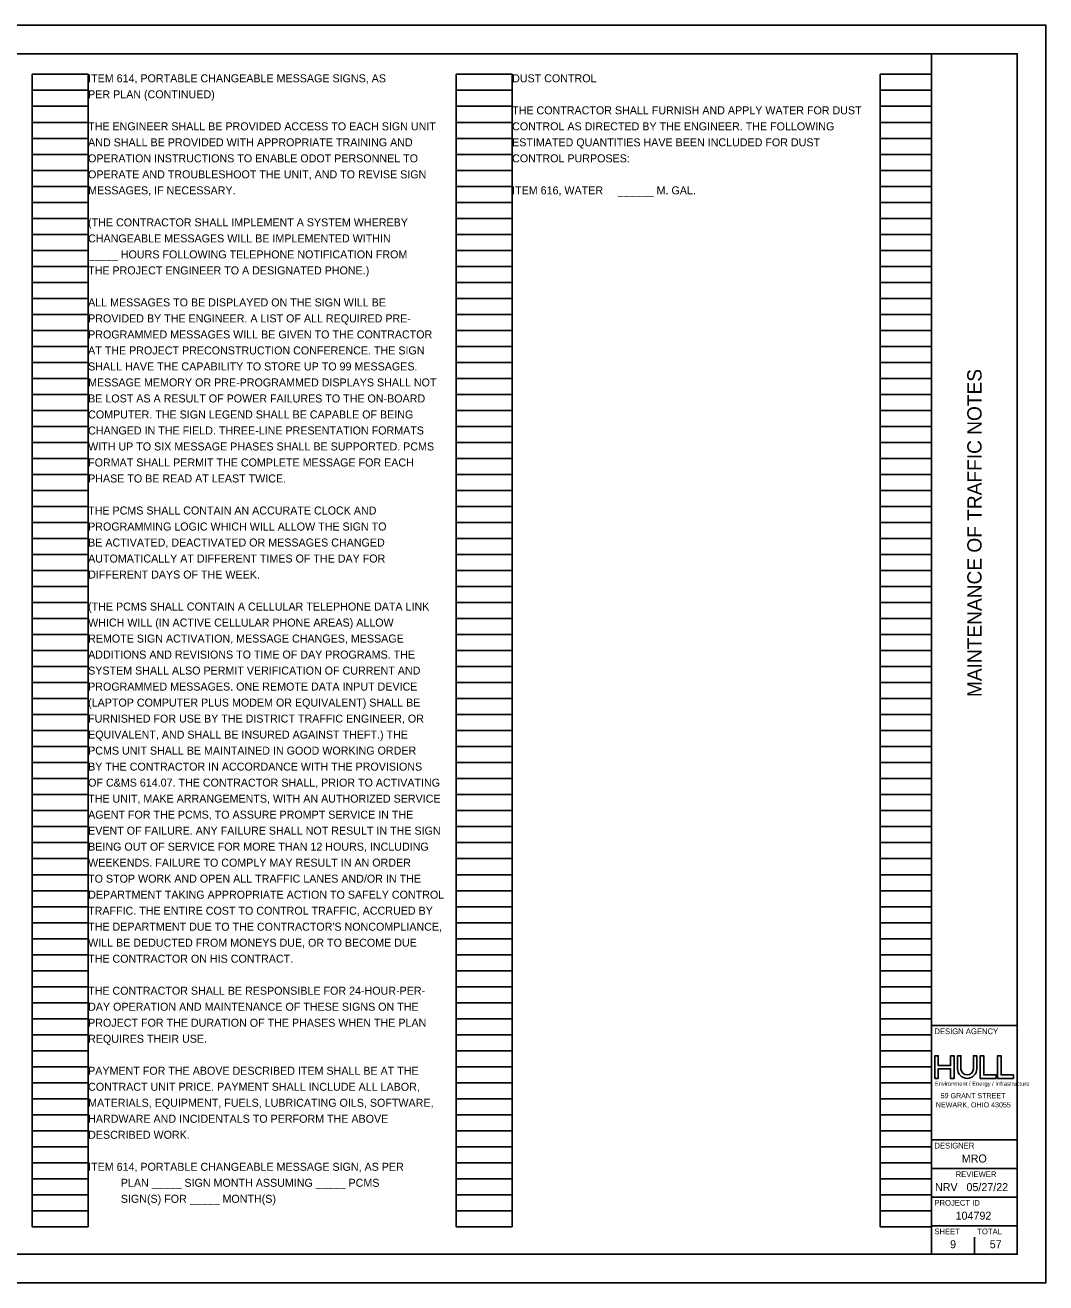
# Model space of a CAD drawing. Extents: x -7.5 to 34, y 0 to 22.
# Drawn here: x 16.14 to 34, y 0 to 22 of the extents above; entities that cross this region are included whole.
import ezdxf

# ---------------------------------------------------------------- set-up
doc = ezdxf.new("R2010")
doc.units = 0
for name, color, linetype in [('Default', 7, 'Continuous'), ('SH_Border', 7, 'Continuous'), ('SH_Cut_Line', 7, 'Continuous'), ('SH_Data', 7, 'Continuous'), ('SH_Text', 7, 'Continuous')]:
    doc.layers.add(name, color=color, linetype=linetype)

msp = doc.modelspace()

# ---------------------------------------------------------------- linework, layer by layer
at = {"layer": 'Default'}
for p, q in [((32.623, 3.637), (32.623, 3.637)), ((32.623, 3.637), (32.623, 3.637)), ((32.623, 3.577), (32.623, 3.577))]:
    msp.add_line(p, q, dxfattribs=at)
for points in [[(32.394, 3.973), (32.333, 3.973), (32.333, 3.799), (32.118, 3.799), (32.118, 3.973), (32.058, 3.973), (32.058, 3.577), (32.118, 3.577), (32.118, 3.745), (32.333, 3.745), (32.333, 3.577), (32.394, 3.577)], [(32.912, 3.973), (32.852, 3.973), (32.852, 3.577), (33.128, 3.577), (33.128, 3.637), (32.912, 3.637)], [(32.852, 3.973), (32.852, 3.577), (33.128, 3.577), (33.128, 3.637), (32.912, 3.637), (32.912, 3.973)], [(33.217, 3.973), (33.156, 3.973), (33.156, 3.577), (33.433, 3.577), (33.433, 3.637), (33.217, 3.637)], [(33.156, 3.973), (33.156, 3.577), (33.433, 3.577), (33.433, 3.637), (33.217, 3.637), (33.217, 3.973)]]:
    msp.add_lwpolyline(points, close=True, dxfattribs=at)
for points in [[(32.394, 3.973), (32.394, 3.973), (32.394, 3.577), (32.333, 3.577), (32.333, 3.745), (32.118, 3.745), (32.118, 3.577), (32.058, 3.577), (32.058, 3.973), (32.118, 3.973), (32.118, 3.799), (32.333, 3.799), (32.333, 3.973), (32.394, 3.973)], [(32.514, 3.746), (32.514, 3.973), (32.454, 3.973), (32.454, 3.746)], [(32.454, 3.746), (32.454, 3.973), (32.514, 3.973), (32.514, 3.746)], [(32.792, 3.746), (32.792, 3.973), (32.731, 3.973), (32.731, 3.746)], [(32.731, 3.746), (32.731, 3.973), (32.792, 3.973), (32.792, 3.746)]]:
    msp.add_lwpolyline(points, dxfattribs=at)
for radius, start, end in [(0.169, 180, 270.0443), (0.169, 180, 270), (0.108, 180, 270), (0.108, 180, 270), (0.108, 270, 0), (0.169, 269.9557, 0), (0.108, 270, 0), (0.169, 270, 0)]:
    msp.add_arc((32.623, 3.746), radius, start, end, dxfattribs=at)
at = {"layer": 'SH_Border'}
for p, q in [((32, 0.5), (32, 21.5)), ((32, 4.5), (33.5, 4.5)), ((32, 2.5), (33.5, 2.5)), ((32, 2), (33.5, 2)), ((32, 1.5), (33.5, 1.5)), ((32, 1), (33.5, 1))]:
    msp.add_line(p, q, dxfattribs=at)
msp.add_lwpolyline([(1.5, 21.5), (33.5, 21.5), (33.5, 0.5), (1.5, 0.5)], close=True, dxfattribs=at)
at = {"layer": 'SH_Cut_Line'}
msp.add_lwpolyline([(0, 0), (34, 0), (34, 22), (0, 22)], close=True, dxfattribs=at)
at = {"layer": 'SH_Data'}
for p, q in [((16.26, 0.98), (16.26, 21.14)), ((16.26, 21.14), (17.24, 21.14)), ((17.24, 0.98), (17.24, 21.14)), ((23.68, 0.98), (23.68, 21.14)), ((23.68, 21.14), (24.66, 21.14)), ((24.66, 0.98), (24.66, 21.14)), ((31.1, 0.98), (31.1, 21.14)), ((31.1, 21.14), (32, 21.14)), ((32, 0.98), (32, 21.14)), ((16.26, 20.86), (17.24, 20.86)), ((23.68, 20.86), (24.66, 20.86)), ((31.1, 20.86), (32, 20.86)), ((16.26, 20.58), (17.24, 20.58)), ((23.68, 20.58), (24.66, 20.58)), ((31.1, 20.58), (32, 20.58)), ((16.26, 20.3), (17.24, 20.3)), ((23.68, 20.3), (24.66, 20.3)), ((31.1, 20.3), (32, 20.3)), ((16.26, 20.02), (17.24, 20.02)), ((23.68, 20.02), (24.66, 20.02)), ((31.1, 20.02), (32, 20.02)), ((16.26, 19.74), (17.24, 19.74)), ((23.68, 19.74), (24.66, 19.74)), ((31.1, 19.74), (32, 19.74)), ((16.26, 19.46), (17.24, 19.46)), ((23.68, 19.46), (24.66, 19.46)), ((31.1, 19.46), (32, 19.46)), ((16.26, 19.18), (17.24, 19.18)), ((23.68, 19.18), (24.66, 19.18)), ((31.1, 19.18), (32, 19.18)), ((16.26, 18.9), (17.24, 18.9)), ((23.68, 18.9), (24.66, 18.9)), ((31.1, 18.9), (32, 18.9)), ((16.26, 18.62), (17.24, 18.62)), ((23.68, 18.62), (24.66, 18.62)), ((31.1, 18.62), (32, 18.62)), ((16.26, 18.34), (17.24, 18.34)), ((23.68, 18.34), (24.66, 18.34)), ((31.1, 18.34), (32, 18.34)), ((16.26, 18.06), (17.24, 18.06)), ((23.68, 18.06), (24.66, 18.06)), ((31.1, 18.06), (32, 18.06)), ((16.26, 17.78), (17.24, 17.78)), ((23.68, 17.78), (24.66, 17.78)), ((31.1, 17.78), (32, 17.78)), ((16.26, 17.5), (17.24, 17.5)), ((23.68, 17.5), (24.66, 17.5)), ((31.1, 17.5), (32, 17.5)), ((16.26, 17.22), (17.24, 17.22)), ((23.68, 17.22), (24.66, 17.22)), ((31.1, 17.22), (32, 17.22)), ((16.26, 16.94), (17.24, 16.94)), ((23.68, 16.94), (24.66, 16.94)), ((31.1, 16.94), (32, 16.94)), ((16.26, 16.66), (17.24, 16.66)), ((23.68, 16.66), (24.66, 16.66)), ((31.1, 16.66), (32, 16.66)), ((16.26, 16.38), (17.24, 16.38)), ((23.68, 16.38), (24.66, 16.38)), ((31.1, 16.38), (32, 16.38)), ((16.26, 16.1), (17.24, 16.1)), ((23.68, 16.1), (24.66, 16.1)), ((31.1, 16.1), (32, 16.1)), ((16.26, 15.82), (17.24, 15.82)), ((23.68, 15.82), (24.66, 15.82)), ((31.1, 15.82), (32, 15.82)), ((16.26, 15.54), (17.24, 15.54)), ((23.68, 15.54), (24.66, 15.54)), ((31.1, 15.54), (32, 15.54)), ((16.26, 15.26), (17.24, 15.26)), ((23.68, 15.26), (24.66, 15.26)), ((31.1, 15.26), (32, 15.26)), ((16.26, 14.98), (17.24, 14.98)), ((23.68, 14.98), (24.66, 14.98)), ((31.1, 14.98), (32, 14.98)), ((16.26, 14.7), (17.24, 14.7)), ((23.68, 14.7), (24.66, 14.7)), ((31.1, 14.7), (32, 14.7)), ((16.26, 14.42), (17.24, 14.42)), ((23.68, 14.42), (24.66, 14.42)), ((31.1, 14.42), (32, 14.42)), ((16.26, 14.14), (17.24, 14.14)), ((23.68, 14.14), (24.66, 14.14)), ((31.1, 14.14), (32, 14.14)), ((16.26, 13.86), (17.24, 13.86)), ((23.68, 13.86), (24.66, 13.86)), ((31.1, 13.86), (32, 13.86)), ((16.26, 13.58), (17.24, 13.58)), ((23.68, 13.58), (24.66, 13.58)), ((31.1, 13.58), (32, 13.58)), ((16.26, 13.3), (17.24, 13.3)), ((23.68, 13.3), (24.66, 13.3)), ((31.1, 13.3), (32, 13.3)), ((16.26, 13.02), (17.24, 13.02)), ((23.68, 13.02), (24.66, 13.02)), ((31.1, 13.02), (32, 13.02)), ((16.26, 12.74), (17.24, 12.74)), ((23.68, 12.74), (24.66, 12.74)), ((31.1, 12.74), (32, 12.74)), ((16.26, 12.46), (17.24, 12.46)), ((23.68, 12.46), (24.66, 12.46)), ((31.1, 12.46), (32, 12.46)), ((16.26, 12.18), (17.24, 12.18)), ((23.68, 12.18), (24.66, 12.18)), ((31.1, 12.18), (32, 12.18)), ((16.26, 11.9), (17.24, 11.9)), ((23.68, 11.9), (24.66, 11.9)), ((31.1, 11.9), (32, 11.9)), ((16.26, 11.62), (17.24, 11.62)), ((23.68, 11.62), (24.66, 11.62)), ((31.1, 11.62), (32, 11.62)), ((16.26, 11.34), (17.24, 11.34)), ((23.68, 11.34), (24.66, 11.34)), ((31.1, 11.34), (32, 11.34)), ((16.26, 11.06), (17.24, 11.06)), ((23.68, 11.06), (24.66, 11.06)), ((31.1, 11.06), (32, 11.06)), ((16.26, 10.78), (17.24, 10.78)), ((23.68, 10.78), (24.66, 10.78)), ((31.1, 10.78), (32, 10.78)), ((16.26, 10.5), (17.24, 10.5)), ((23.68, 10.5), (24.66, 10.5)), ((31.1, 10.5), (32, 10.5)), ((16.26, 10.22), (17.24, 10.22)), ((23.68, 10.22), (24.66, 10.22)), ((31.1, 10.22), (32, 10.22)), ((16.26, 9.94), (17.24, 9.94)), ((23.68, 9.94), (24.66, 9.94)), ((31.1, 9.94), (32, 9.94)), ((16.26, 9.66), (17.24, 9.66)), ((23.68, 9.66), (24.66, 9.66)), ((31.1, 9.66), (32, 9.66)), ((16.26, 9.38), (17.24, 9.38)), ((23.68, 9.38), (24.66, 9.38)), ((31.1, 9.38), (32, 9.38)), ((16.26, 9.1), (17.24, 9.1)), ((23.68, 9.1), (24.66, 9.1)), ((31.1, 9.1), (32, 9.1)), ((16.26, 8.82), (17.24, 8.82)), ((23.68, 8.82), (24.66, 8.82)), ((31.1, 8.82), (32, 8.82)), ((16.26, 8.54), (17.24, 8.54)), ((23.68, 8.54), (24.66, 8.54)), ((31.1, 8.54), (32, 8.54)), ((16.26, 8.26), (17.24, 8.26)), ((23.68, 8.26), (24.66, 8.26)), ((31.1, 8.26), (32, 8.26)), ((16.26, 7.98), (17.24, 7.98)), ((23.68, 7.98), (24.66, 7.98)), ((31.1, 7.98), (32, 7.98)), ((16.26, 7.7), (17.24, 7.7)), ((23.68, 7.7), (24.66, 7.7)), ((31.1, 7.7), (32, 7.7)), ((16.26, 7.42), (17.24, 7.42)), ((23.68, 7.42), (24.66, 7.42)), ((31.1, 7.42), (32, 7.42)), ((16.26, 7.14), (17.24, 7.14)), ((23.68, 7.14), (24.66, 7.14)), ((31.1, 7.14), (32, 7.14)), ((16.26, 6.86), (17.24, 6.86)), ((23.68, 6.86), (24.66, 6.86)), ((31.1, 6.86), (32, 6.86)), ((16.26, 6.58), (17.24, 6.58)), ((23.68, 6.58), (24.66, 6.58)), ((31.1, 6.58), (32, 6.58)), ((16.26, 6.3), (17.24, 6.3)), ((23.68, 6.3), (24.66, 6.3)), ((31.1, 6.3), (32, 6.3)), ((16.26, 6.02), (17.24, 6.02)), ((23.68, 6.02), (24.66, 6.02)), ((31.1, 6.02), (32, 6.02)), ((16.26, 5.74), (17.24, 5.74)), ((23.68, 5.74), (24.66, 5.74)), ((31.1, 5.74), (32, 5.74)), ((16.26, 5.46), (17.24, 5.46)), ((23.68, 5.46), (24.66, 5.46)), ((31.1, 5.46), (32, 5.46)), ((16.26, 5.18), (17.24, 5.18)), ((23.68, 5.18), (24.66, 5.18)), ((31.1, 5.18), (32, 5.18)), ((16.26, 4.9), (17.24, 4.9)), ((23.68, 4.9), (24.66, 4.9)), ((31.1, 4.9), (32, 4.9)), ((16.26, 4.62), (17.24, 4.62)), ((23.68, 4.62), (24.66, 4.62)), ((31.1, 4.62), (32, 4.62)), ((16.26, 4.34), (17.24, 4.34)), ((23.68, 4.34), (24.66, 4.34)), ((31.1, 4.34), (32, 4.34)), ((16.26, 4.06), (17.24, 4.06)), ((23.68, 4.06), (24.66, 4.06)), ((31.1, 4.06), (32, 4.06)), ((16.26, 3.78), (17.24, 3.78)), ((23.68, 3.78), (24.66, 3.78)), ((31.1, 3.78), (32, 3.78)), ((16.26, 3.5), (17.24, 3.5)), ((23.68, 3.5), (24.66, 3.5)), ((31.1, 3.5), (32, 3.5)), ((32.75, 3.5), (32.75, 3.5)), ((16.26, 3.22), (17.24, 3.22)), ((23.68, 3.22), (24.66, 3.22)), ((31.1, 3.22), (32, 3.22)), ((16.26, 2.94), (17.24, 2.94)), ((23.68, 2.94), (24.66, 2.94)), ((31.1, 2.94), (32, 2.94)), ((16.26, 2.66), (17.24, 2.66)), ((23.68, 2.66), (24.66, 2.66)), ((31.1, 2.66), (32, 2.66)), ((16.26, 2.38), (17.24, 2.38)), ((23.68, 2.38), (24.66, 2.38)), ((31.1, 2.38), (32, 2.38)), ((16.26, 2.1), (17.24, 2.1)), ((23.68, 2.1), (24.66, 2.1)), ((31.1, 2.1), (32, 2.1)), ((16.26, 1.82), (17.24, 1.82)), ((23.68, 1.82), (24.66, 1.82)), ((31.1, 1.82), (32, 1.82)), ((16.26, 1.54), (17.24, 1.54)), ((23.68, 1.54), (24.66, 1.54)), ((31.1, 1.54), (32, 1.54)), ((16.26, 1.26), (17.24, 1.26)), ((23.68, 1.26), (24.66, 1.26)), ((31.1, 1.26), (32, 1.26)), ((16.26, 0.98), (17.24, 0.98)), ((23.68, 0.98), (24.66, 0.98)), ((31.1, 0.98), (32, 0.98)), ((32.375, 0.675), (32.375, 0.675)), ((32.75, 0.5), (32.75, 0.8))]:
    msp.add_line(p, q, dxfattribs=at)

# ---------------------------------------------------------------- texts
at = {"layer": 'Default'}
msp.add_text('Environment / Energy / Infrastructure ', height=0.07349, dxfattribs=at).set_placement((32.056, 3.447))
at = {"layer": 'SH_Data'}
msp.add_text('MAINTENANCE OF TRAFFIC NOTES', height=0.25, rotation=90, dxfattribs=at).set_placement((32.875, 10.247))
for s, height, p in [('DESIGN AGENCY', 0.1, (32.05, 4.35)), ('DESIGNER', 0.1, (32.05, 2.35)), ('MRO', 0.14, (32.529, 2.105)), ('REVIEWER', 0.1, (32.422, 1.85)), ('NRV', 0.14, (32.06, 1.605)), ('05/27/22', 0.14, (32.611, 1.605)), ('PROJECT ID', 0.1, (32.05, 1.35)), ('104792', 0.14, (32.421, 1.105)), ('SHEET', 0.1, (32.05, 0.85)), ('TOTAL', 0.1, (32.8, 0.85)), ('9', 0.14, (32.325, 0.605)), ('57', 0.14, (33.018, 0.605))]:
    msp.add_text(s, height=height, dxfattribs=at).set_placement(p)
at = {"layer": 'SH_Text'}
for s, height, p in [('ITEM 614, PORTABLE CHANGEABLE MESSAGE SIGNS, AS', 0.14, (17.24, 21)), ('DUST CONTROL', 0.14, (24.66, 21)), ('PER PLAN (CONTINUED)', 0.14, (17.24, 20.72)), ('THE CONTRACTOR SHALL FURNISH AND APPLY WATER FOR DUST', 0.14, (24.66, 20.44)), ('THE ENGINEER SHALL BE PROVIDED ACCESS TO EACH SIGN UNIT', 0.14, (17.24, 20.16)), ('CONTROL AS DIRECTED BY THE ENGINEER. THE FOLLOWING', 0.14, (24.66, 20.16)), ('AND SHALL BE PROVIDED WITH APPROPRIATE TRAINING AND', 0.14, (17.24, 19.88)), ('ESTIMATED QUANTITIES HAVE BEEN INCLUDED FOR DUST', 0.14, (24.66, 19.88)), ('OPERATION INSTRUCTIONS TO ENABLE ODOT PERSONNEL TO', 0.14, (17.24, 19.6)), ('CONTROL PURPOSES:', 0.14, (24.66, 19.6)), ('OPERATE AND TROUBLESHOOT THE UNIT, AND TO REVISE SIGN', 0.14, (17.24, 19.32)), ('MESSAGES, IF NECESSARY.', 0.14, (17.24, 19.04)), ('ITEM 616, WATER     ______ M. GAL.', 0.14, (24.66, 19.04)), ('(THE CONTRACTOR SHALL IMPLEMENT A SYSTEM WHEREBY', 0.14, (17.24, 18.48)), ('CHANGEABLE MESSAGES WILL BE IMPLEMENTED WITHIN', 0.14, (17.24, 18.2)), ('_____ HOURS FOLLOWING TELEPHONE NOTIFICATION FROM', 0.14, (17.24, 17.92)), ('THE PROJECT ENGINEER TO A DESIGNATED PHONE.)', 0.14, (17.24, 17.64)), ('ALL MESSAGES TO BE DISPLAYED ON THE SIGN WILL BE', 0.14, (17.24, 17.08)), ('PROVIDED BY THE ENGINEER. A LIST OF ALL REQUIRED PRE-', 0.14, (17.24, 16.8)), ('PROGRAMMED MESSAGES WILL BE GIVEN TO THE CONTRACTOR', 0.14, (17.24, 16.52)), ('AT THE PROJECT PRECONSTRUCTION CONFERENCE. THE SIGN', 0.14, (17.24, 16.24)), ('SHALL HAVE THE CAPABILITY TO STORE UP TO 99 MESSAGES.', 0.14, (17.24, 15.96)), ('MESSAGE MEMORY OR PRE-PROGRAMMED DISPLAYS SHALL NOT', 0.14, (17.24, 15.68)), ('BE LOST AS A RESULT OF POWER FAILURES TO THE ON-BOARD', 0.14, (17.24, 15.4)), ('COMPUTER. THE SIGN LEGEND SHALL BE CAPABLE OF BEING', 0.14, (17.24, 15.12)), ('CHANGED IN THE FIELD. THREE-LINE PRESENTATION FORMATS', 0.14, (17.24, 14.84)), ('WITH UP TO SIX MESSAGE PHASES SHALL BE SUPPORTED. PCMS', 0.14, (17.24, 14.56)), ('FORMAT SHALL PERMIT THE COMPLETE MESSAGE FOR EACH', 0.14, (17.24, 14.28)), ('PHASE TO BE READ AT LEAST TWICE.', 0.14, (17.24, 14)), ('THE PCMS SHALL CONTAIN AN ACCURATE CLOCK AND', 0.14, (17.24, 13.44)), ('PROGRAMMING LOGIC WHICH WILL ALLOW THE SIGN TO', 0.14, (17.24, 13.16)), ('BE ACTIVATED, DEACTIVATED OR MESSAGES CHANGED', 0.14, (17.24, 12.88)), ('AUTOMATICALLY AT DIFFERENT TIMES OF THE DAY FOR', 0.14, (17.24, 12.6)), ('DIFFERENT DAYS OF THE WEEK.', 0.14, (17.24, 12.32)), ('(THE PCMS SHALL CONTAIN A CELLULAR TELEPHONE DATA LINK', 0.14, (17.24, 11.76)), ('WHICH WILL (IN ACTIVE CELLULAR PHONE AREAS) ALLOW', 0.14, (17.24, 11.48)), ('REMOTE SIGN ACTIVATION, MESSAGE CHANGES, MESSAGE', 0.14, (17.24, 11.2)), ('ADDITIONS AND REVISIONS TO TIME OF DAY PROGRAMS. THE', 0.14, (17.24, 10.92)), ('SYSTEM SHALL ALSO PERMIT VERIFICATION OF CURRENT AND', 0.14, (17.24, 10.64)), ('PROGRAMMED MESSAGES. ONE REMOTE DATA INPUT DEVICE', 0.14, (17.24, 10.36)), ('(LAPTOP COMPUTER PLUS MODEM OR EQUIVALENT) SHALL BE', 0.14, (17.24, 10.08)), ('FURNISHED FOR USE BY THE DISTRICT TRAFFIC ENGINEER, OR', 0.14, (17.24, 9.8)), ('EQUIVALENT, AND SHALL BE INSURED AGAINST THEFT.) THE', 0.14, (17.24, 9.52)), ('PCMS UNIT SHALL BE MAINTAINED IN GOOD WORKING ORDER', 0.14, (17.24, 9.24)), ('BY THE CONTRACTOR IN ACCORDANCE WITH THE PROVISIONS', 0.14, (17.24, 8.96)), ('OF C&MS 614.07. THE CONTRACTOR SHALL, PRIOR TO ACTIVATING', 0.14, (17.24, 8.68)), ('THE UNIT, MAKE ARRANGEMENTS, WITH AN AUTHORIZED SERVICE', 0.14, (17.24, 8.4)), ('AGENT FOR THE PCMS, TO ASSURE PROMPT SERVICE IN THE', 0.14, (17.24, 8.12)), ('EVENT OF FAILURE. ANY FAILURE SHALL NOT RESULT IN THE SIGN', 0.14, (17.24, 7.84)), ('BEING OUT OF SERVICE FOR MORE THAN 12 HOURS, INCLUDING', 0.14, (17.24, 7.56)), ('WEEKENDS. FAILURE TO COMPLY MAY RESULT IN AN ORDER', 0.14, (17.24, 7.28)), ('TO STOP WORK AND OPEN ALL TRAFFIC LANES AND/OR IN THE', 0.14, (17.24, 7)), ('DEPARTMENT TAKING APPROPRIATE ACTION TO SAFELY CONTROL', 0.14, (17.24, 6.72)), ('TRAFFIC. THE ENTIRE COST TO CONTROL TRAFFIC, ACCRUED BY', 0.14, (17.24, 6.44)), ("THE DEPARTMENT DUE TO THE CONTRACTOR'S NONCOMPLIANCE,", 0.14, (17.24, 6.16)), ('WILL BE DEDUCTED FROM MONEYS DUE, OR TO BECOME DUE', 0.14, (17.24, 5.88)), ('THE CONTRACTOR ON HIS CONTRACT.', 0.14, (17.24, 5.6)), ('THE CONTRACTOR SHALL BE RESPONSIBLE FOR 24-HOUR-PER-', 0.14, (17.24, 5.04)), ('DAY OPERATION AND MAINTENANCE OF THESE SIGNS ON THE', 0.14, (17.24, 4.76)), ('PROJECT FOR THE DURATION OF THE PHASES WHEN THE PLAN', 0.14, (17.24, 4.48)), ('REQUIRES THEIR USE.', 0.14, (17.24, 4.2)), ('PAYMENT FOR THE ABOVE DESCRIBED ITEM SHALL BE AT THE', 0.14, (17.24, 3.64)), ('CONTRACT UNIT PRICE. PAYMENT SHALL INCLUDE ALL LABOR,', 0.14, (17.24, 3.36)), ('59 GRANT STREET', 0.09, (32.159, 3.229)), ('MATERIALS, EQUIPMENT, FUELS, LUBRICATING OILS, SOFTWARE,', 0.14, (17.24, 3.08)), ('NEWARK, OHIO 43055', 0.09, (32.075, 3.069)), ('HARDWARE AND INCIDENTALS TO PERFORM THE ABOVE', 0.14, (17.24, 2.8)), ('DESCRIBED WORK.', 0.14, (17.24, 2.52)), ('ITEM 614, PORTABLE CHANGEABLE MESSAGE SIGN, AS PER', 0.14, (17.24, 1.96)), ('           PLAN _____ SIGN MONTH ASSUMING _____ PCMS', 0.14, (17.24, 1.68)), ('           SIGN(S) FOR _____ MONTH(S)', 0.14, (17.24, 1.4))]:
    msp.add_text(s, height=height, dxfattribs=at).set_placement(p)

doc.saveas('drawing.dxf')
